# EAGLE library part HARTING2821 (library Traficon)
Harting TB 09 06 215 2821 DIN41612 type H, 15 pins socket
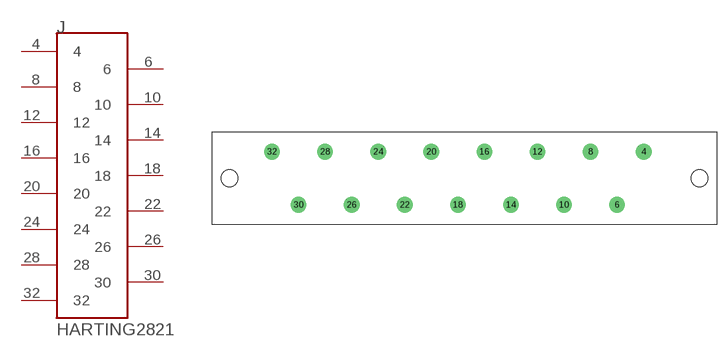
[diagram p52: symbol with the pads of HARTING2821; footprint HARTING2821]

Designator prefix J

## HARTING2821  [HARTING2821]
4  4
6  6
8  8
10  10
12  12
14  14
16  16
18  18
20  20
22  22
24  24
26  26
28  28
30  30
32  32

## Footprint HARTING2821 (pad centres in mm)
drill 2 round: 4 34.29,10.16; 6 29.21,0; 8 24.13,10.16; 10 19.05,0; 12 13.97,10.16; 14 8.89,0; 16 3.81,10.16; 18 -1.27,0; 20 -6.35,10.16; 22 -11.43,0; 24 -16.51,10.16; 26 -21.59,0; 28 -26.67,10.16; 30 -31.75,0; 32 -36.83,10.16
hole 3.2 at -45,5.08
hole 3.2 at 45,5.08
